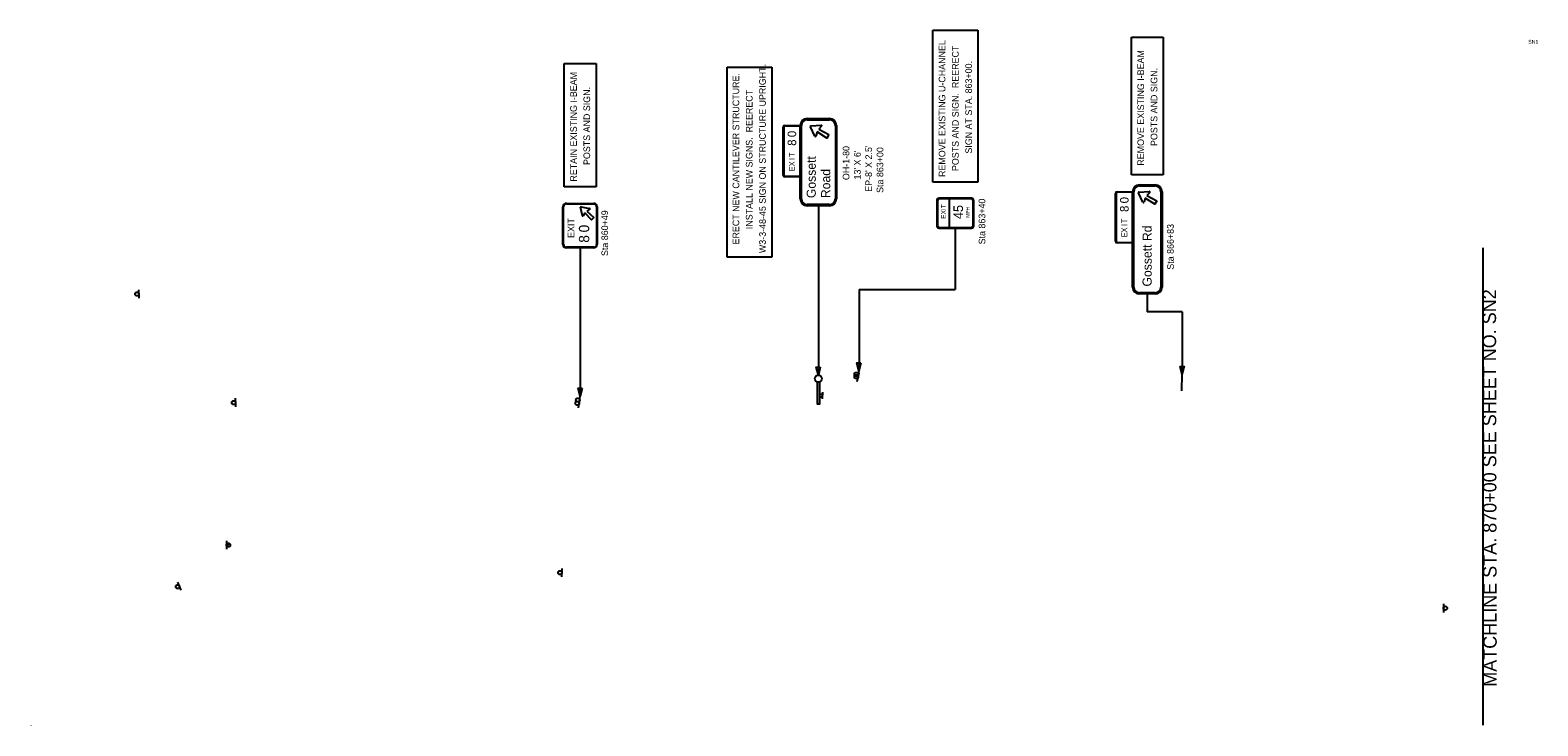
# Model space of a CAD drawing. Extents: x 1738774 to 1740361, y 1163468 to 1164201.
import ezdxf

# ---------------------------------------------------------------- set-up
doc = ezdxf.new("R2010")
doc.units = 0
for name, color, linetype in [('DateStamp', 7, 'Continuous'), ('Default', 7, 'Continuous'), ('ICE_LOGO', 7, 'Continuous'), ('NotForConst', 7, 'Continuous')]:
    doc.layers.add(name, color=color, linetype=linetype)

msp = doc.modelspace()

# ---------------------------------------------------------------- linework, layer by layer
at = {"layer": 'DateStamp'}
msp.add_lwpolyline([(1740303.7, 1163469.1), (1740303.7, 1163744), (1740303.7, 1163971.6)], dxfattribs=at)
at = {"layer": 'ICE_LOGO'}
for p, q in [((1739724.1, 1164041), (1739724.1, 1164201)), ((1739724.1, 1164201), (1739771.7, 1164201)), ((1739771.7, 1164201), (1739771.7, 1164041)), ((1739933.3, 1164048.6), (1739933.3, 1164193.6)), ((1739933.3, 1164193.6), (1739966.9, 1164193.6)), ((1739966.9, 1164193.6), (1739966.9, 1164048.6)), ((1739336, 1164036), (1739336, 1164166)), ((1739336, 1164166), (1739369.7, 1164166)), ((1739369.7, 1164166), (1739369.7, 1164036)), ((1739507.8, 1163962), (1739507.8, 1164161.9)), ((1739507.8, 1164161.9), (1739554.6, 1164161.9)), ((1739554.6, 1164161.9), (1739554.6, 1163962)), ((1739591.8, 1164107.8), (1739615.6, 1164107.8)), ((1739591.8, 1164106.6), (1739615.6, 1164106.6)), ((1739771.7, 1164041), (1739724.1, 1164041)), ((1739966.9, 1164048.6), (1739933.3, 1164048.6)), ((1739941.8, 1164038.1), (1739958.4, 1164038.1)), ((1739369.7, 1164036), (1739336, 1164036)), ((1739764.9, 1164023.9), (1739731, 1164023.9)), ((1739764.9, 1164023.2), (1739731, 1164023.2)), ((1739741.7, 1163993.2), (1739741.7, 1164023.2)), ((1739941.8, 1164036.9), (1739958.4, 1164036.9)), ((1739334.8, 1163975.4), (1739334.8, 1164015)), ((1739335.4, 1163975.4), (1739335.4, 1164015)), ((1739338.4, 1164018.6), (1739367.2, 1164018.6)), ((1739338.4, 1164018), (1739367.2, 1164018)), ((1739370.2, 1164015), (1739370.2, 1163975.4)), ((1739370.8, 1164015), (1739370.8, 1163975.4)), ((1739615.6, 1164017.3), (1739591.8, 1164017.3)), ((1739615.6, 1164016.1), (1739591.8, 1164016.1)), ((1739603.7, 1164016.1), (1739603.7, 1163837.7)), ((1739728.4, 1164021.4), (1739728.4, 1163995)), ((1739729.2, 1164021.4), (1739729.2, 1163995)), ((1739766.7, 1163995), (1739766.7, 1164021.4)), ((1739767.4, 1163995), (1739767.4, 1164021.4)), ((1739731, 1163993.2), (1739764.9, 1163993.2)), ((1739731, 1163992.4), (1739764.9, 1163992.4)), ((1739747.9, 1163992.7), (1739747.9, 1163927.9)), ((1739367.2, 1163972.4), (1739338.4, 1163972.4)), ((1739367.2, 1163971.8), (1739338.4, 1163971.8)), ((1739352.8, 1163971.8), (1739352.8, 1163815.7)), ((1739554.6, 1163962), (1739507.8, 1163962)), ((1738888.5, 1163918.6), (1738888.2, 1163927.6)), ((1739646.6, 1163927.9), (1739646.6, 1163842.5)), ((1739646.6, 1163927.9), (1739747.9, 1163927.9)), ((1739958.4, 1163924.4), (1739941.8, 1163924.4)), ((1739958.4, 1163923.2), (1739941.8, 1163923.2)), ((1739950.1, 1163923.2), (1739950.1, 1163904.2)), ((1739986.9, 1163904.2), (1739950.1, 1163904.2)), ((1739986.9, 1163904.2), (1739986.9, 1163838.8)), ((1739644.6, 1163831.1), (1739646.7, 1163839.9)), ((1739644.8, 1163833.7), (1739646.6, 1163842.5)), ((1739986.6, 1163821), (1739986.9, 1163838.8)), ((1739352, 1163806.8), (1739352.8, 1163815.7)), ((1739605.2, 1163817.5), (1739608, 1163817.5)), ((1739608, 1163819.6), (1739607.9, 1163812.6)), ((1738990.4, 1163804.4), (1738989.8, 1163813.3)), ((1739351.3, 1163803.2), (1739352.6, 1163812.1)), ((1739605.2, 1163814.8), (1739608, 1163814.8)), ((1738980.5, 1163663.2), (1738980.4, 1163654.2)), ((1738981.2, 1163659.4), (1738982.9, 1163660.3)), ((1738981.5, 1163660.7), (1738982.5, 1163659)), ((1739333.6, 1163625.1), (1739333.8, 1163634)), ((1738932.6, 1163611.3), (1738929.4, 1163619.7)), ((1740261.9, 1163596.7), (1740261.9, 1163587.7))]:
    msp.add_line(p, q, dxfattribs=at)
for points in [[(1739566.6, 1164048.4), (1739566.6, 1164098.8)], [(1739567.2, 1164098.8), (1739567.2, 1164048.4)], [(1739568.4, 1164100.6), (1739584.6, 1164100.6), (1739584.6, 1164100)], [(1739584.6, 1164100), (1739568.4, 1164100)], [(1739584.6, 1164023.3), (1739584.6, 1164100.6)], [(1739585.8, 1164023.3), (1739585.8, 1164100.6)], [(1739600.1, 1164089.4), (1739595.3, 1164099.2)], [(1739595.8, 1164100.1), (1739606.6, 1164100.8)], [(1739602.4, 1164093.8), (1739601.2, 1164089.5)], [(1739614.6, 1164091.1), (1739612.5, 1164087.4), (1739602.4, 1164093.8)], [(1739607.1, 1164099.8), (1739604.1, 1164096.6)], [(1739604.1, 1164096.6), (1739614.6, 1164091.1)], [(1739621.6, 1164100.6), (1739621.6, 1164023.3)], [(1739622.8, 1164100.6), (1739622.8, 1164023.3)], [(1739568.4, 1164047.2), (1739584.6, 1164047.2), (1739584.6, 1164046.6), (1739568.4, 1164046.6)], [(1739916.6, 1163978.7), (1739916.6, 1164029.1)], [(1739917.2, 1164029.1), (1739917.2, 1163978.7)], [(1739918.4, 1164030.9), (1739934.6, 1164030.9), (1739934.6, 1164030.3)], [(1739934.6, 1164030.3), (1739918.4, 1164030.3)], [(1739934.6, 1163930.4), (1739934.6, 1164030.9)], [(1739935.8, 1163930.4), (1739935.8, 1164030.9)], [(1739945.5, 1164019.8), (1739940.8, 1164029.5)], [(1739941.3, 1164030.4), (1739952.1, 1164031.1)], [(1739947.9, 1164024.1), (1739946.7, 1164019.8)], [(1739960, 1164021.4), (1739957.9, 1164017.8), (1739947.9, 1164024.1)], [(1739952.6, 1164030.1), (1739949.5, 1164026.9)], [(1739949.5, 1164026.9), (1739960, 1164021.4)], [(1739964.4, 1164030.9), (1739964.4, 1163930.4)], [(1739965.6, 1164030.9), (1739965.6, 1163930.4)], [(1739355.2, 1164005.6), (1739353.4, 1164014.5)], [(1739354, 1164015), (1739362.8, 1164013.3)], [(1739357.9, 1164008.6), (1739356, 1164005.5)], [(1739367.2, 1164003.8), (1739364.7, 1164001.2), (1739357.9, 1164008.6)], [(1739363, 1164012.4), (1739359.8, 1164010.5)], [(1739359.8, 1164010.5), (1739367.2, 1164003.8)], [(1739918.4, 1163977.5), (1739934.6, 1163977.5), (1739934.6, 1163976.9), (1739918.4, 1163976.9)], [(1739602.5, 1163830.5), (1739602.3, 1163807.4), (1739605.1, 1163807.4), (1739605.3, 1163830.7)], [(1738981.7, 1163658.9), (1738981.6, 1163658.9), (1738981.4, 1163659), (1738981.3, 1163659.1), (1738981.2, 1163659.3), (1738981.1, 1163659.4), (1738981.1, 1163659.6), (1738981, 1163659.7), (1738981, 1163659.9), (1738981, 1163660.1), (1738981.1, 1163660.2), (1738981.2, 1163660.4), (1738981.3, 1163660.5), (1738981.4, 1163660.6), (1738981.5, 1163660.7), (1738981.7, 1163660.8), (1738981.8, 1163660.8), (1738982, 1163660.8), (1738982.2, 1163660.8), (1738982.3, 1163660.8)], [(1738982.3, 1163660.8), (1738982.5, 1163660.7), (1738982.6, 1163660.7), (1738982.7, 1163660.6), (1738982.8, 1163660.4), (1738982.9, 1163660.3), (1738983, 1163660.1), (1738983, 1163660), (1738983, 1163659.8), (1738983, 1163659.6), (1738983, 1163659.5), (1738982.9, 1163659.3), (1738982.8, 1163659.2), (1738982.7, 1163659.1), (1738982.5, 1163659), (1738982.4, 1163658.9), (1738982.2, 1163658.9), (1738982, 1163658.8), (1738981.9, 1163658.9), (1738981.7, 1163658.9)]]:
    msp.add_lwpolyline(points, dxfattribs=at)
for points in [[(1739648.5, 1163850.7), (1739646.5, 1163842.5), (1739644.4, 1163850.7)], [(1739605.6, 1163846), (1739603.7, 1163837.7), (1739601.5, 1163845.9)], [(1739988.8, 1163847), (1739986.9, 1163838.8), (1739984.7, 1163846.9)], [(1739354.9, 1163823.9), (1739352.8, 1163815.7), (1739350.8, 1163823.9)]]:
    msp.add_lwpolyline(points, close=True, dxfattribs=at)
for centre, radius in [((1738886.3, 1163923.1), 2), ((1739603.7, 1163834), 3.71), ((1739643.7, 1163838.5), 2), ((1739643.7, 1163836), 2), ((1738988.1, 1163808.7), 2), ((1739349.9, 1163808), 2), ((1739350.4, 1163811.5), 2), ((1738982.5, 1163658.7), 2), ((1739331.7, 1163629.6), 2), ((1738929.1, 1163614.8), 2), ((1740263.9, 1163592.2), 2)]:
    msp.add_circle(centre, radius, dxfattribs=at)
for centre, radius, start, end in [((1739591.8, 1164100.6), 7.2, 90, 180), ((1739591.8, 1164100.6), 6, 90, 180), ((1739615.6, 1164100.6), 7.2, 0, 90), ((1739615.6, 1164100.6), 6, 0, 90), ((1739568.4, 1164098.8), 1.8, 90, 180), ((1739568.4, 1164098.8), 1.2, 90, 180), ((1739595.8, 1164099.5), 0.6, 94.0194, 205.9807), ((1739600.6, 1164089.7), 0.6, 205.9807, 343.4461), ((1739606.7, 1164100.2), 0.6, 316.5539, 94.0194), ((1739568.4, 1164048.4), 1.8, 180, 270), ((1739568.4, 1164048.4), 1.2, 180, 270), ((1739941.8, 1164030.9), 7.2, 90, 180), ((1739958.4, 1164030.9), 7.2, 0, 90), ((1739591.8, 1164023.3), 7.2, 180, 270), ((1739591.8, 1164023.3), 6, 180, 270), ((1739615.6, 1164023.3), 6, 270, 0), ((1739615.6, 1164023.3), 7.2, 270, 0), ((1739731, 1164021.4), 2.55, 90.0006, 179.9996), ((1739731, 1164021.4), 1.8, 90, 180), ((1739764.9, 1164021.4), 2.55, 360, 90), ((1739764.9, 1164021.4), 1.8, 0, 90), ((1739918.4, 1164029.1), 1.8, 90, 180), ((1739918.4, 1164029.1), 1.2, 90, 180), ((1739941.8, 1164030.9), 6, 90, 180), ((1739941.3, 1164029.8), 0.6, 94.0194, 205.9807), ((1739952.2, 1164030.5), 0.6, 316.5539, 94.0194), ((1739958.4, 1164030.9), 6, 0, 90), ((1739338.4, 1164015), 3.6, 90, 180), ((1739338.4, 1164015), 3, 90, 180), ((1739353.9, 1164014.6), 0.45, 78.8221, 191.1779), ((1739362.7, 1164012.8), 0.45, 301.0379, 78.8221), ((1739367.2, 1164015), 3.6, 360, 90), ((1739367.2, 1164015), 3, 360, 90), ((1739946.1, 1164020), 0.6, 205.9807, 343.4461), ((1739355.6, 1164005.7), 0.45, 191.1779, 328.9621), ((1739731, 1163995), 2.55, 180, 270), ((1739731, 1163995), 1.8, 180, 270), ((1739764.9, 1163995), 1.8, 270, 360), ((1739764.9, 1163995), 2.55, 269.9996, 0.0004), ((1739338.4, 1163975.4), 3.6, 180, 270), ((1739338.4, 1163975.4), 3, 180, 270), ((1739367.2, 1163975.4), 3, 270, 360), ((1739367.2, 1163975.4), 3.6, 270, 360), ((1739918.4, 1163978.7), 1.8, 180, 270), ((1739918.4, 1163978.7), 1.2, 180, 270), ((1739941.8, 1163930.4), 7.2, 180, 270), ((1739941.8, 1163930.4), 6, 180, 270), ((1739958.4, 1163930.4), 7.2, 270, 0), ((1739958.4, 1163930.4), 6, 270, 0)]:
    msp.add_arc(centre, radius, start, end, dxfattribs=at)

# ---------------------------------------------------------------- texts
at = {"layer": 'Default'}
for s, p in [('Sheet: 1', (1738773.7, 1163468.8)), ('Angle:  16.0848', (1738773.7, 1163468.6)), ('Align: A_I85', (1738773.7, 1163468.3))]:
    msp.add_text(s, height=0.208, dxfattribs=at).set_placement(p)
at = {"layer": 'ICE_LOGO'}
for s, height, rotation, p in [('REMOVE EXISTING U-CHANNEL', 7, 90.0001, (1739737.5, 1164046.4)), ('POSTS AND SIGN.  REERECT', 7, 90.0001, (1739751.5, 1164052.6)), ('W3-3-48-45 SIGN ON STRUCTURE UPRIGHT.', 7, 90.0001, (1739548.4, 1163966.2)), ('SIGN AT STA. 863+00.', 7, 90.0001, (1739765.5, 1164071)), ('REMOVE EXISTING I-BEAM', 7, 90.0001, (1739946.7, 1164058.3)), ('RETAIN EXISTING I-BEAM', 7, 90.0001, (1739349.4, 1164041.5)), ('ERECT NEW CANTILEVER STRUCTURE.', 7, 90.0001, (1739520.4, 1163975.3)), ('POSTS AND SIGN. ', 7, 90.0001, (1739960.7, 1164079)), ('POSTS AND SIGN.', 7, 90.0001, (1739363.4, 1164059)), ('INSTALL NEW SIGNS.  REERECT', 7, 90.0001, (1739534.4, 1163991.4)), ('0', 9, 90, (1739580.4, 1164088.3)), ('8', 9, 90, (1739580.4, 1164079.2)), ('T', 6, 90, (1739578.9, 1164067.3)), ('OH-1-80', 7, 90.0001, (1739636.4, 1164043.1)), ("13' X 6'", 7, 90.0001, (1739648.3, 1164043.7)), ("EP-8' X 2.5'", 7, 90.0001, (1739660.2, 1164030.8)), ('Sta 863+00', 7, 90.0001, (1739672.1, 1164029.6)), ('I', 6, 90, (1739578.9, 1164064.3)), ('X', 6, 90, (1739578.9, 1164057.5)), ('E', 6, 90, (1739578.9, 1164052.4)), ('Gossett', 9.6, 90, (1739601, 1164024.1)), ('Road', 9.6, 90, (1739616.2, 1164024.1)), ('Sta 863+40', 7, 90.0001, (1739779.5, 1163975.4)), ('0', 9, 90, (1739930.4, 1164018.6)), ('Sta 860+49', 7, 90.0001, (1739382.3, 1163963.1)), ('EXIT', 5, 90, (1739737.9, 1164002.3)), ('45', 10, 90, (1739756, 1164002)), ('MPH', 3.75, 90, (1739762.9, 1164003.4)), ('8', 9, 90, (1739930.4, 1164009.5)), ('EXIT', 7, 90, (1739346.8, 1163982.2)), ('0', 10.8, 90, (1739362.4, 1163988)), ('T', 6, 90, (1739928.9, 1163997.6)), ('I', 6, 90, (1739928.9, 1163994.6)), ('X', 6, 90, (1739928.9, 1163987.8)), ('Gossett Rd', 9.6, 90, (1739954.7, 1163931)), ('Sta 866+83', 7, 90.0001, (1739978, 1163948.7)), ('8', 10.8, 90, (1739362.4, 1163977.1)), ('E', 6, 90, (1739928.9, 1163982.7))]:
    msp.add_text(s, height=height, rotation=rotation, dxfattribs=at).set_placement(p)
at = {"layer": 'NotForConst'}
msp.add_text('SN1', height=4, dxfattribs=at).set_placement((1740351.2, 1164186.8))
msp.add_text('MATCHLINE STA. 870+00 SEE SHEET NO. SN2', height=14.173, rotation=90.1124, dxfattribs=at).set_placement((1740318.1, 1163509.4))

doc.saveas('drawing.dxf')
